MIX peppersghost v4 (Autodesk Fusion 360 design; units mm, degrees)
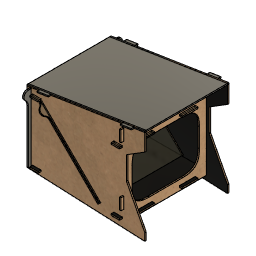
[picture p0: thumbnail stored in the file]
parameter "mat" = 3.175
parameter "device" = 165.1
parameter "chip" = 2.54
sketch "Sketch1" plane through (0, 0, 0) normal (0, 0, 1) x axis (1, 0, 0)
  line L1 (82.55, 82.55) -> (-82.55, 82.55)
  line L2 (82.55, -82.55) -> (82.55, 82.55)
  line L3 (-82.55, -82.55) -> (82.55, -82.55)
  line L4 (-82.55, 82.55) -> (-82.55, -82.55)
  line L5 (82.55, -82.55) -> (-82.55, 82.55)
  line L6 (-82.55, -82.55) -> (82.55, 82.55)
  line L7 (-101.6, -101.6) -> (101.6, -101.6)
  line L8 (-101.6, 101.6) -> (-101.6, -101.6)
  line L9 (101.6, 101.6) -> (-101.6, 101.6)
  line L10 (101.6, -101.6) -> (101.6, 101.6)
  point P6 (0, 0)
  point P1 (0, 0)
  horizontal L1
  perpendicular L1 L2
  parallel L1 L3
  parallel L2 L4
  coincident L5 P6
  coincident L6 P6
  coincident P1 P6
  dimension "d3" distance L2 L4 = 165.1 (= "device")
  dimension "d4" distance L1 L3 = 165.1 (= "device")
  dimension "d5" = -19.05
extrude "Extrude1" new body sketch "Sketch1" profile of L1 L2 L3 L4 L9 L8 L7 L10 along normal blind 3.175 bodies "top glass"
sketch "Sketch5" plane through (0, 0, 3.175) normal (0, 0, 1) x axis (-1, 0, 0)
  line L1 (101.6, -101.6) -> (-101.6, -101.6)
  line L2 (101.6, 101.6) -> (101.6, -101.6)
  line L3 (-101.6, 101.6) -> (101.6, 101.6)
  line L4 (-101.6, -101.6) -> (-101.6, 101.6)
  line L5 (-82.55, 92.075) -> (82.55, 92.075)
  line L6 (-82.55, 101.6) -> (-82.55, 92.075)
  line L7 (82.55, 101.6) -> (-82.55, 101.6)
  line L8 (82.55, 92.075) -> (82.55, 101.6)
  line L9 (-2.5, 0) -> (-20, 0)
  line L10 (82.55, -101.6) -> (-82.55, -101.6)
  line L11 (82.55, -92.075) -> (82.55, -101.6)
  line L12 (-82.55, -101.6) -> (-82.55, -92.075)
  line L13 (-82.55, -92.075) -> (82.55, -92.075)
  point P6 (82.55, 92.075)
  point P14 (82.55, -92.075)
  point P7 (-82.55, 92.075)
  point P15 (-82.55, -92.075)
  point P8 (-82.55, 101.6)
  point P12 (-82.55, -101.6)
  point P9 (82.55, 101.6)
  point P13 (82.55, -101.6)
  horizontal L5
  vertical L6
  horizontal L7
  vertical L8
  midpoint L3 L7
  symmetric P6 L9 P14
  symmetric P7 L9 P15
  symmetric P8 L9 P12
  symmetric P9 L9 P13
  dimension "d14" distance L5 L7 = 9.525 (= "mat + 0.25 in")
  dimension "d15" distance L2 L8 = 19.05
extrude "Extrude3" cut sketch "Sketch5" profile of L1 L3 L5 L6 L7 L8 L10 L11 L12 L13 to an object
work_plane "WorkPlane2" AlongDistance -92.075
sketch "Sketch6" plane through (0, -92.075, 0) normal (0, 1, 0) x axis (1, 0, 0)
  line L1 (152.4, -57.2749) -> (-114.3, -57.2749)
  line L2 (152.4, 158.6251) -> (152.4, -57.2749)
  line L3 (-114.3, 158.6251) -> (152.4, 158.6251)
  line L4 (-114.3, -57.2749) -> (-114.3, 158.6251)
  line L5 (-82.55, 0) -> (82.55, 0)
  line L6 (82.55, -3.175) -> (-82.55, -3.175)
  line L7 (-82.55, -3.175) -> (-101.6, -3.175)
  line L8 (-101.6, -3.175) -> (-101.6, 0)
  line L9 (-101.6, 0) -> (-82.55, 0)
  line L10 (82.55, 0) -> (101.6, 0)
  line L11 (101.6, -3.175) -> (101.6, 0)
  line L12 (101.6, -3.175) -> (82.55, -3.175)
  line L13 (-114.3, -15.4458) -> (152.4, -57.2749)
  line L14 (-114.3, 146.7191) -> (152.4, 158.6251)
  line L15 (110.9761, 61.5737) -> (152.4, 141.4625)
  line L16 (110.9761, 9.6217) -> (110.9761, 61.5737)
  line L17 (152.4, -16.1863) -> (110.9761, 9.6217)
  line L18 (57.3922, 143.0683) -> (-80.2184, 5.4578)
  line L19 (104.4264, 125.521) -> (104.4264, 5.9873)
  point P14 (-114.3, -15.4458)
  point P15 (-114.3, 146.7191)
  point P16 (152.4, 141.4625)
  point P19 (152.4, -16.1863)
  point P11 (-101.6, 0)
  point P12 (101.6, 0)
  horizontal L1
  vertical L2
  horizontal L3
  vertical L4
  coincident L4 P14
  coincident L4 P15
  coincident L2 P16
  parallel L2 L16
  coincident L2 P19
  perpendicular L5 L19
  dimension "d19" distance L4 P11 = 12.7
  dimension "d20" distance L2 P12 = 50.8
  dimension "d21" distance L1 L3 = 215.9
  dimension "d22" angle L5 L18 = 45
extrude "Extrude4" new body sketch "Sketch6" profile of L2 L4 L5 L6 L7 L8 L9 L10 L11 L12 L13 L14 L15 L16 L17 no distance stored bodies "side1"
mirror "Mirror1" mirrorStitchTolerance 0.1016 bodies "side2"
combine "Combine1"
combine "Combine2"
sketch "Sketch8" plane through (0, 0, 3.175) normal (0, 0, 1) x axis (-1, 0, 0)
  line L1 (-82.55, 101.6) -> (-82.55, 92.075)
  line L2 (-101.6, 101.6) -> (-82.55, 101.6)
  line L3 (-101.6, -101.6) -> (-101.6, 101.6)
  line L4 (-82.55, -101.6) -> (-101.6, -101.6)
  line L5 (-82.55, -92.075) -> (-82.55, -101.6)
  line L6 (82.55, -92.075) -> (-82.55, -92.075)
  line L7 (82.55, -101.6) -> (82.55, -92.075)
  line L8 (101.6, -101.6) -> (82.55, -101.6)
  line L9 (101.6, 101.6) -> (101.6, -101.6)
  line L10 (82.55, 101.6) -> (101.6, 101.6)
  line L11 (82.55, 92.075) -> (82.55, 101.6)
  line L12 (-82.55, 92.075) -> (82.55, 92.075)
  line L13 (-101.6, 66.675) -> (-111.125, 66.675)
  line L14 (-101.6, 31.115) -> (-101.6, 66.675)
  line L15 (-111.125, 31.115) -> (-101.6, 31.115)
  line L16 (-111.125, 66.675) -> (-111.125, 31.115)
  line L17 (114.3, 92.075) -> (-152.4, 92.075)
  line L18 (-152.4, 95.25) -> (-152.4, 92.075)
  line L19 (-152.4, 95.25) -> (114.3, 95.25)
  line L20 (114.3, 95.25) -> (114.3, 92.075)
  line L21 (-2.5, 0) -> (-20, 0)
  line L22 (-101.6, -31.115) -> (-101.6, -66.675)
  line L23 (-111.125, -31.115) -> (-101.6, -31.115)
  line L24 (-111.125, -66.675) -> (-111.125, -31.115)
  line L25 (-101.6, -66.675) -> (-111.125, -66.675)
  point P14 (-111.125, 66.675)
  point P27 (-111.125, -66.675)
  point P15 (-101.6, 66.675)
  point P24 (-101.6, -66.675)
  point P16 (-101.6, 31.115)
  point P25 (-101.6, -31.115)
  point P17 (-111.125, 31.115)
  point P26 (-111.125, -31.115)
  horizontal L13
  vertical L14
  horizontal L15
  vertical L16
  collinear L3 L14
  symmetric P14 L21 P27
  symmetric P15 L21 P24
  symmetric P16 L21 P25
  symmetric P17 L21 P26
  dimension "d27" distance L13 L17 = 25.4
  dimension "d28" distance L14 L16 = 9.525 (= "mat + 0.25 in")
extrude "Extrude5" add sketch "Sketch8" profile of L3 L13 L14 L15 L16 L22 L23 L24 L25 to an object
copy_paste_bodies "CopyPasteBodies2"
move "Move2"
combine "Combine5"
combine "Combine6"
sketch "Sketch9" plane through (101.6, 0, 0) normal (1, 0, 0) x axis (0, 1, 0)
  line L1 (31.115, 3.175) -> (31.115, 0)
  line L2 (-31.115, 3.175) -> (31.115, 3.175)
  line L3 (-31.115, 0) -> (-31.115, 3.175)
  line L4 (31.115, 0) -> (-31.115, 0)
  line L5 (-101.6, 3.175) -> (-101.6, 0)
  line L6 (101.6, 0) -> (-101.6, 0)
  line L7 (-101.6, 3.175) -> (101.6, 3.175)
  line L8 (101.6, 3.175) -> (101.6, 0)
  line L9 (-92.075, -146.7191) -> (-92.075, -158.6251)
  line L10 (-92.075, 15.4458) -> (-92.075, -146.7191)
  line L11 (-92.075, 15.4458) -> (-92.075, 57.2749)
  line L12 (-95.25, -158.6251) -> (-92.075, -158.6251)
  line L13 (-95.25, -158.6251) -> (-95.25, -146.7191)
  line L14 (-95.25, -146.7191) -> (-95.25, 15.4458)
  line L15 (-95.25, 15.4458) -> (-95.25, 57.2749)
  line L16 (-95.25, 57.2749) -> (-92.075, 57.2749)
  line L17 (92.075, 15.4458) -> (92.075, 57.2749)
  line L18 (92.075, 15.4458) -> (92.075, -146.7191)
  line L19 (92.075, -146.7191) -> (92.075, -158.6251)
  line L20 (95.25, -158.6251) -> (95.25, -146.7191)
  line L21 (95.25, -158.6251) -> (92.075, -158.6251)
  line L22 (95.25, -146.7191) -> (95.25, 15.4458)
  line L23 (95.25, 57.2749) -> (92.075, 57.2749)
  line L24 (95.25, 15.4458) -> (95.25, 57.2749)
  line L25 (-92.075, -146.7191) -> (92.075, -146.7191)
  line L26 (-92.075, 45.8529) -> (-92.075, -146.7191)
  line L27 (92.075, 45.8529) -> (-92.075, 45.8529)
  line L28 (92.075, -146.7191) -> (92.075, 45.8529)
  line L29 (-101.6, 39.02) -> (-92.075, 39.02)
  line L30 (-101.6, 13.62) -> (-101.6, 39.02)
  line L31 (-92.075, 13.62) -> (-101.6, 13.62)
  line L32 (-92.075, 39.02) -> (-92.075, 13.62)
  line L33 (-101.6, -119.6596) -> (-92.075, -119.6596)
  line L34 (-101.6, -94.2596) -> (-101.6, -119.6596)
  line L35 (-92.075, -94.2596) -> (-101.6, -94.2596)
  line L36 (-92.075, -119.6596) -> (-92.075, -94.2596)
  line L37 (0, -146.7191) -> (0, 45.8529)
  line L38 (92.075, 39.02) -> (92.075, 13.62)
  line L39 (101.6, 39.02) -> (92.075, 39.02)
  line L40 (92.075, 13.62) -> (101.6, 13.62)
  line L41 (101.6, 13.62) -> (101.6, 39.02)
  line L42 (92.075, -119.6596) -> (92.075, -94.2596)
  line L43 (101.6, -119.6596) -> (92.075, -119.6596)
  line L44 (92.075, -94.2596) -> (101.6, -94.2596)
  line L45 (101.6, -94.2596) -> (101.6, -119.6596)
  point P28 (-92.075, 45.8529)
  point P20 (92.075, -146.7191)
  point P26 (92.075, -146.7191)
  point P30 (-92.075, 39.02)
  point P34 (-92.075, -119.6596)
  point P38 (0, 45.8529)
  point P39 (0, -146.7191)
  point P41 (92.075, 39.02)
  point P31 (-101.6, 39.02)
  point P42 (101.6, 39.02)
  point P32 (-101.6, 13.62)
  point P43 (101.6, 13.62)
  point P33 (-92.075, 13.62)
  point P40 (92.075, 13.62)
  point P45 (92.075, -119.6596)
  point P35 (-101.6, -119.6596)
  point P46 (101.6, -119.6596)
  point P36 (-101.6, -94.2596)
  point P47 (101.6, -94.2596)
  point P37 (-92.075, -94.2596)
  point P44 (92.075, -94.2596)
  horizontal L25
  vertical L26
  horizontal L27
  vertical L28
  coincident L11 P28
  coincident P20 P26
  horizontal L29
  vertical L30
  horizontal L31
  vertical L32
  coincident L26 P30
  horizontal L33
  vertical L34
  horizontal L35
  vertical L36
  coincident L10 P34
  midpoint L27 P38
  midpoint L25 P39
  symmetric P30 L37 P41
  symmetric P31 L37 P42
  symmetric P32 L37 P43
  symmetric P33 L37 P40
  symmetric P34 L37 P45
  symmetric P35 L37 P46
  symmetric P36 L37 P47
  symmetric P37 L37 P44
  dimension "d31" distance L29 L31 = 25.4
  dimension "d32" distance L26 L30 = 9.525 (= "mat + 0.25 in")
  dimension "d33" distance L33 L35 = 25.4
  dimension "d34" distance L26 L34 = 9.525 (= "mat + 0.25 in")
extrude "Extrude6" new body sketch "Sketch9" profile of L1 L2 L3 L4 L6 L7 L10 L11 L14 L15 L17 L18 L22 L24 L25 L26 L27 L28 L29 L30 L31 L32 L33 L34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 along normal blind 3.175 (= "mat") bodies "faceplat"
combine "Combine7"
combine "Combine8"
combine "Combine11"
combine "Combine12"
sketch "Sketch11" plane through (104.775, 0, 0) normal (1, 0, 0) x axis (0, 1, 0)
  line L1 (31.115, -136.525) -> (31.115, -139.7)
  line L2 (66.675, -136.525) -> (31.115, -136.525)
  line L3 (66.675, -139.7) -> (66.675, -136.525)
  line L4 (31.115, -139.7) -> (66.675, -139.7)
  line L5 (-66.675, -136.525) -> (-66.675, -139.7)
  line L6 (-31.115, -136.525) -> (-66.675, -136.525)
  line L7 (-31.115, -139.7) -> (-31.115, -136.525)
  line L8 (-66.675, -139.7) -> (-31.115, -139.7)
  line L9 (31.115, 3.175) -> (31.115, 0)
  line L10 (66.675, 3.175) -> (31.115, 3.175)
  line L11 (66.675, 0) -> (66.675, 3.175)
  line L12 (31.115, 0) -> (66.675, 0)
  line L13 (-66.675, 3.175) -> (-66.675, 0)
  line L14 (-31.115, 3.175) -> (-66.675, 3.175)
  line L15 (-31.115, 0) -> (-31.115, 3.175)
  line L16 (-66.675, 0) -> (-31.115, 0)
  line L17 (101.6, -119.6596) -> (92.075, -119.6596)
  line L18 (101.6, -94.2596) -> (101.6, -119.6596)
  line L19 (92.075, -94.2596) -> (101.6, -94.2596)
  line L20 (92.075, 13.62) -> (92.075, -94.2596)
  line L21 (101.6, 13.62) -> (92.075, 13.62)
  line L22 (101.6, 39.02) -> (101.6, 13.62)
  line L23 (92.075, 39.02) -> (101.6, 39.02)
  line L24 (92.075, 45.8529) -> (92.075, 39.02)
  line L25 (-92.075, 45.8529) -> (92.075, 45.8529)
  line L26 (-92.075, 39.02) -> (-92.075, 45.8529)
  line L27 (-101.6, 39.02) -> (-92.075, 39.02)
  line L28 (-101.6, 13.62) -> (-101.6, 39.02)
  line L29 (-92.075, 13.62) -> (-101.6, 13.62)
  line L30 (-92.075, -94.2596) -> (-92.075, 13.62)
  line L31 (-101.6, -94.2596) -> (-92.075, -94.2596)
  line L32 (-101.6, -119.6596) -> (-101.6, -94.2596)
  line L33 (-92.075, -119.6596) -> (-101.6, -119.6596)
  line L34 (-92.075, -146.7191) -> (-92.075, -119.6596)
  line L35 (92.075, -146.7191) -> (-92.075, -146.7191)
  line L36 (92.075, -119.6596) -> (92.075, -146.7191)
  line L37 (76.2, -5.08) -> (-76.2, -5.08)
  line L38 (76.2, -124.46) -> (76.2, -5.08)
  line L39 (-76.2, -124.46) -> (76.2, -124.46)
  line L40 (-76.2, -5.08) -> (-76.2, -124.46)
  horizontal L37
  vertical L38
  horizontal L39
  vertical L40
extrude "Extrude7" cut sketch "Sketch11" profile of L37 L38 L39 L40 to an object
fillet "Fillet1" radius 38.1
sketch "Sketch12" plane through (0, 0, 0) normal (0, 1, 0) x axis (1, 0, 0)
  line L1 (52.4196, 133.0004) -> (-80.5808, 0)
  line L2 (50.1745, 135.2455) -> (52.4196, 133.0004)
  line L3 (-82.8258, 2.2451) -> (50.1745, 135.2455)
  line L4 (-80.5808, 0) -> (-82.8258, 2.2451)
  line L5 (82.55, 0) -> (-82.55, 0)
  point P2 (-80.5808, 0)
  point P5 (-82.8258, 2.2451)
  perpendicular L1 L2
  parallel L1 L3
  parallel L2 L4
  coincident P2 L5
  dimension "d41" distance P2 P5 = 3.175
  dimension "d42" angle L1 L5 = 45
extrude "Extrude8" new body sketch "Sketch12" profile of L1 L2 L3 L4 distance 99.06 bodies "reflector"
sketch "Sketch13" plane through (-40.2904, 0, -40.2904) normal (0.7071, 0, 0.7071) x axis (0, 1, 0)
  line L1 (99.06, -131.1117) -> (-99.06, -131.1117)
  line L2 (99.06, 56.9792) -> (99.06, -131.1117)
  line L3 (-99.06, 56.9792) -> (99.06, 56.9792)
  line L4 (-99.06, -131.1117) -> (-99.06, 56.9792)
  line L5 (-92.075, -22.9237) -> (-92.075, -219.928)
  line L6 (-92.075, 91.7442) -> (-92.075, -22.9237)
  line L7 (-95.25, -219.928) -> (-92.075, -219.928)
  line L8 (-95.25, -219.928) -> (-95.25, -22.9237)
  line L9 (-95.25, -22.9237) -> (-95.25, 91.7442)
  line L10 (-95.25, 91.7442) -> (-92.075, 91.7442)
  line L11 (-92.075, -131.1117) -> (-95.25, -131.1117)
  line L12 (-92.075, -121.5867) -> (-92.075, -131.1117)
  line L13 (-95.25, -121.5867) -> (-92.075, -121.5867)
  line L14 (-95.25, -131.1117) -> (-95.25, -121.5867)
  line L15 (0, -106.68) -> (0, -131.1117)
  line L16 (0, -106.68) -> (0, -131.1117)
  line L17 (92.075, -121.5867) -> (92.075, -131.1117)
  line L18 (95.25, -121.5867) -> (92.075, -121.5867)
  line L19 (92.075, -131.1117) -> (95.25, -131.1117)
  line L20 (95.25, -131.1117) -> (95.25, -121.5867)
  circle C1 centre (99.06, 41.3822) radius 9.525
  circle C2 centre (-99.06, 41.3822) radius 9.525
  point P12 (-95.25, -131.1117)
  point P16 (0, -131.1117)
  point P23 (95.25, -131.1117)
  point P13 (-92.075, -131.1117)
  point P20 (92.075, -131.1117)
  point P14 (-92.075, -121.5867)
  point P21 (92.075, -121.5867)
  point P15 (-95.25, -121.5867)
  point P22 (95.25, -121.5867)
  point P18 (0, -131.1117)
  point P17 (0, -106.68)
  point P19 (0, -106.68)
  point P24 (99.06, 41.3822)
  horizontal L11
  vertical L12
  horizontal L13
  vertical L14
  coincident L8 P12
  coincident L1 P12
  midpoint L1 P16
  perpendicular L1 L15
  symmetric P12 L15 P23
  symmetric P13 L15 P20
  symmetric P14 L15 P21
  symmetric P15 L15 P22
  symmetric P16 L15 P18
  symmetric P17 L15 P19
  coincident L2 P24
  symmetric L16 C1 C2
  dimension "d45" distance P12 P15 = 9.525
  dimension "d46" distance L12 L14 = 3.175 (= "mat")
  dimension "d49" diameter C1 = 19.05
combine "Combine13"
combine "Combine14"
extrude "Extrude9" cut sketch "Sketch13" profile of L1 L5 L8 L11 L12 L13 L14 L17 L18 L19 L20 to an object
extrude "Extrude10" add sketch "Sketch13" profile of L2 L4 C1 C2 to an object
fillet "Fillet2" radius 7.62
work_plane "WorkPlane3" AlongDistance 50.8
sketch "Sketch14" plane through (19.05, -146.05, -50.6751) normal (0, -1, 0) x axis (-1, 0, 0)
sketch "side panel" plane through (19.05, -146.05, -50.6751) normal (0, -1, 0) x axis (-1, 0, 0)
  line L1 (99.6308, -50.6751) -> (-33.3696, 82.3253)
  line L2 (101.8758, -48.4301) -> (99.6308, -50.6751)
  line L3 (-31.1245, 84.5703) -> (101.8758, -48.4301)
  line L4 (-33.3696, 82.3253) -> (-31.1245, 84.5703)
  line L5 (-85.725, 68.9845) -> (-82.55, 68.9845)
  line L6 (-85.725, -64.2951) -> (-82.55, -64.2951)
  line L7 (-82.55, -64.2951) -> (-82.55, -89.6951)
  line L8 (-82.55, 68.9845) -> (-82.55, 43.5845)
  line L9 (-85.725, -89.6951) -> (-85.725, -64.2951)
  line L10 (-82.55, 43.5845) -> (-85.725, 43.5845)
  line L11 (-82.55, -89.6951) -> (-85.725, -89.6951)
  line L12 (-85.725, 43.5845) -> (-85.725, 68.9845)
  line L13 (-63.5, 85.8499) -> (-82.55, 85.8499)
  line L14 (-63.5, 89.0249) -> (-63.5, 85.8499)
  line L15 (-82.55, 89.0249) -> (-63.5, 89.0249)
  line L16 (-82.55, 85.8499) -> (-82.55, 89.0249)
  line L17 (-82.55, -53.8501) -> (-82.55, -50.6751)
  line L18 (-63.5, -53.8501) -> (-82.55, -53.8501)
  line L19 (-63.5, -50.6751) -> (-63.5, -53.8501)
  line L20 (-82.55, -50.6751) -> (-63.5, -50.6751)
  line L21 (-133.35, 107.95) -> (-133.35, 90.7873)
  line L22 (133.35, 96.0439) -> (-133.35, 107.95)
  line L23 (133.35, -66.121) -> (133.35, 96.0439)
  line L24 (133.35, -66.121) -> (-133.35, -107.95)
  line L25 (-133.35, -66.8614) -> (-133.35, -107.95)
  line L26 (-133.35, -66.8614) -> (-91.9261, -41.0534)
  line L27 (-91.9261, -41.0534) -> (-91.9261, 10.8985)
  line L28 (-91.9261, 10.8985) -> (-133.35, 90.7873)
  line L29 (120.65, -53.8501) -> (101.6, -53.8501)
  line L30 (120.65, -50.6751) -> (120.65, -53.8501)
  line L31 (101.6, -50.6751) -> (120.65, -50.6751)
  line L32 (101.6, -53.8501) -> (101.6, -50.6751)
  line L33 (120.65, 85.8499) -> (101.6, 85.8499)
  line L34 (120.65, 89.0249) -> (120.65, 85.8499)
  line L35 (101.6, 89.0249) -> (120.65, 89.0249)
  line L36 (101.6, 85.8499) -> (101.6, 89.0249)
work_plane "WorkPlane4" AlongDistance 50.8
sketch "top glass" plane through (4.7625, 0, 53.975) normal (0, 0, 1) x axis (1, 0, 0)
  line L1 (106.3625, 66.675) -> (106.3625, 31.115)
  line L2 (96.8375, 66.675) -> (106.3625, 66.675)
  line L3 (106.3625, 31.115) -> (96.8375, 31.115)
  line L4 (96.8375, 66.675) -> (96.8375, 101.6)
  line L5 (96.8375, -31.115) -> (96.8375, 31.115)
  line L6 (106.3625, -31.115) -> (106.3625, -66.675)
  line L7 (96.8375, -31.115) -> (106.3625, -31.115)
  line L8 (106.3625, -66.675) -> (96.8375, -66.675)
  line L9 (96.8375, -101.6) -> (96.8375, -66.675)
  line L10 (-87.3125, -101.6) -> (-87.3125, -92.075)
  line L11 (77.7875, -92.075) -> (77.7875, -101.6)
  line L12 (-87.3125, -92.075) -> (77.7875, -92.075)
  line L13 (-87.3125, 92.075) -> (-87.3125, 101.6)
  line L14 (77.7875, 92.075) -> (-87.3125, 92.075)
  line L15 (77.7875, 101.6) -> (77.7875, 92.075)
  line L16 (-106.3625, -101.6) -> (-87.3125, -101.6)
  line L17 (-106.3625, 101.6) -> (-106.3625, -101.6)
  line L18 (-87.3125, 101.6) -> (-106.3625, 101.6)
  line L19 (96.8375, 101.6) -> (77.7875, 101.6)
  line L20 (77.7875, -101.6) -> (96.8375, -101.6)
work_plane "WorkPlane5" AlongDistance 50.8
sketch "faceplate" plane through (155.575, 0, -50.4331) normal (1, 0, 0) x axis (0, 1, 0)
  curve K1 (38.1, -74.0269) -> (76.2, -35.9269)
  line L1 (76.2, 7.2531) -> (76.2, -35.9269)
  curve K2 (-76.2, -35.9269) -> (-38.1, -74.0269)
  line L2 (38.1, -74.0269) -> (-38.1, -74.0269)
  curve K3 (76.2, 7.2531) -> (38.1, 45.3531)
  line L3 (-38.1, 45.3531) -> (38.1, 45.3531)
  curve K4 (-38.1, 45.3531) -> (-76.2, 7.2531)
  line L4 (-76.2, -35.9269) -> (-76.2, 7.2531)
  line L5 (66.675, -86.0919) -> (66.675, -89.2669)
  line L6 (-31.115, -86.0919) -> (-31.115, -89.2669)
  line L7 (-31.115, -89.2669) -> (-66.675, -89.2669)
  line L8 (66.675, -89.2669) -> (31.115, -89.2669)
  line L9 (-66.675, -86.0919) -> (-31.115, -86.0919)
  line L10 (31.115, -89.2669) -> (31.115, -86.0919)
  line L11 (-66.675, -89.2669) -> (-66.675, -86.0919)
  line L12 (31.115, -86.0919) -> (66.675, -86.0919)
  line L13 (92.075, -96.286) -> (92.075, -69.2265)
  line L14 (-92.075, -96.286) -> (92.075, -96.286)
  line L15 (-92.075, -69.2265) -> (-92.075, -96.286)
  line L16 (-101.6, -69.2265) -> (-92.075, -69.2265)
  line L17 (-101.6, -43.8265) -> (-101.6, -69.2265)
  line L18 (-92.075, -43.8265) -> (-101.6, -43.8265)
  line L19 (-92.075, 64.0531) -> (-92.075, -43.8265)
  line L20 (-92.075, 64.0531) -> (-101.6, 64.0531)
  line L21 (-101.6, 64.0531) -> (-101.6, 89.4531)
  line L22 (-101.6, 89.4531) -> (-92.075, 89.4531)
  line L23 (-92.075, 96.286) -> (-92.075, 89.4531)
  line L24 (92.075, 96.286) -> (-92.075, 96.286)
  line L25 (92.075, 89.4531) -> (92.075, 96.286)
  line L26 (101.6, 89.4531) -> (92.075, 89.4531)
  line L27 (101.6, 64.0531) -> (101.6, 89.4531)
  line L28 (92.075, 64.0531) -> (101.6, 64.0531)
  line L29 (92.075, -43.8265) -> (92.075, 64.0531)
  line L30 (92.075, -43.8265) -> (101.6, -43.8265)
  line L31 (101.6, -43.8265) -> (101.6, -69.2265)
  line L32 (101.6, -69.2265) -> (92.075, -69.2265)
  line L33 (66.675, 53.6081) -> (66.675, 50.4331)
  line L34 (31.115, 53.6081) -> (66.675, 53.6081)
  line L35 (31.115, 50.4331) -> (31.115, 53.6081)
  line L36 (66.675, 50.4331) -> (31.115, 50.4331)
  line L37 (-31.115, 53.6081) -> (-31.115, 50.4331)
  line L38 (-66.675, 53.6081) -> (-31.115, 53.6081)
  line L39 (-66.675, 50.4331) -> (-66.675, 53.6081)
  line L40 (-31.115, 50.4331) -> (-66.675, 50.4331)
work_plane "WorkPlane6" AlongDistance 50.8
sketch "reflector" plane through (21.8404, 0, -30.5792) normal (0.7071, 0, 0.7071) x axis (0.7071, 0, -0.7071)
  line L1 (-94.0455, 99.06) -> (-93.807, 99.06)
  line L2 (-63.0898, 99.06) -> (94.0455, 99.06)
  line L3 (-93.807, -99.06) -> (-94.0455, -99.06)
  line L4 (94.0455, -99.06) -> (-63.0898, -99.06)
  line L5 (84.5205, -95.25) -> (84.5205, -92.075)
  line L6 (94.0455, -95.25) -> (84.5205, -95.25)
  line L7 (84.5205, -92.075) -> (94.0455, -92.075)
  line L8 (84.5205, 95.25) -> (94.0455, 95.25)
  line L9 (84.5205, 92.075) -> (84.5205, 95.25)
  line L10 (94.0455, 92.075) -> (84.5205, 92.075)
  line L11 (94.0455, -95.25) -> (94.0455, -99.06)
  line L12 (-94.0455, -99.06) -> (-94.0455, 99.06)
  line L13 (94.0455, 99.06) -> (94.0455, 95.25)
  line L14 (94.0455, 92.075) -> (94.0455, -92.075)
  arc A1 centre (-93.807, -106.68) radius 7.62 clockwise from (-93.807, -99.06) to (-86.981, -103.2933)
  arc A2 centre (-78.4484, -99.06) radius 9.525 clockwise from (-69.9159, -103.2933) to (-86.981, -103.2933)
  arc A3 centre (-63.0898, -106.68) radius 7.62 clockwise from (-69.9159, -103.2933) to (-63.0898, -99.06)
  arc A4 centre (-93.807, 106.68) radius 7.62 clockwise from (-86.981, 103.2933) to (-93.807, 99.06)
  arc A5 centre (-78.4484, 99.06) radius 9.525 clockwise from (-86.981, 103.2933) to (-69.9159, 103.2933)
  arc A6 centre (-63.0898, 106.68) radius 7.62 clockwise from (-63.0898, 99.06) to (-69.9159, 103.2933)
sketch "Sketch19" plane through (-5.1085, 0, 32.5714) normal (-0.1549, 0, 0.9879) x axis (0, -1, 0)
  line L1 (92.075, -110.5264) -> (92.075, 159.4339)
  line L2 (95.25, -110.5264) -> (92.075, -110.5264)
  line L3 (95.25, 159.4339) -> (95.25, -110.5264)
  line L4 (92.075, 159.4339) -> (95.25, 159.4339)
  line L5 (-92.075, 159.4339) -> (-92.075, -110.5264)
  line L6 (-95.25, 159.4339) -> (-92.075, 159.4339)
  line L7 (-95.25, -110.5264) -> (-95.25, 159.4339)
  line L8 (-92.075, -110.5264) -> (-95.25, -110.5264)
  line L9 (-95.25, -110.5264) -> (95.25, -110.5264)
  line L10 (-95.25, 159.4339) -> (-95.25, -110.5264)
  line L11 (95.25, 159.4339) -> (-95.25, 159.4339)
  line L12 (95.25, -110.5264) -> (95.25, 159.4339)
  line L13 (101.6, 109.5556) -> (92.075, 109.5556)
  line L14 (92.075, -81.0611) -> (101.6, -81.0611)
  line L15 (-92.075, 109.5556) -> (-101.6, 109.5556)
  line L16 (-101.6, -81.0611) -> (-92.075, -81.0611)
  line L17 (92.075, 109.5556) -> (101.6, 109.5556)
  line L18 (92.075, 134.9545) -> (92.075, 109.5556)
  line L19 (101.6, 134.9545) -> (92.075, 134.9545)
  line L20 (101.6, 109.5556) -> (101.6, 134.9545)
  line L21 (92.075, -81.0611) -> (101.6, -81.0611)
  line L22 (92.075, -55.6611) -> (92.075, -81.0611)
  line L23 (101.6, -55.6611) -> (92.075, -55.6611)
  line L24 (101.6, -81.0611) -> (101.6, -55.6611)
  line L25 (0, 159.4339) -> (0, -110.5264)
  line L26 (-92.075, -55.6611) -> (-92.075, -81.0611)
  line L27 (-101.6, -55.6611) -> (-92.075, -55.6611)
  line L28 (-92.075, -81.0611) -> (-101.6, -81.0611)
  line L29 (-101.6, -81.0611) -> (-101.6, -55.6611)
  line L30 (-92.075, 134.9545) -> (-92.075, 109.5556)
  line L31 (-101.6, 134.9545) -> (-92.075, 134.9545)
  line L32 (-92.075, 109.5556) -> (-101.6, 109.5556)
  line L33 (-101.6, 109.5556) -> (-101.6, 134.9545)
  point P8 (-95.25, 159.4339)
  point P12 (-95.25, 159.4339)
  point P4 (95.25, -110.5264)
  point P10 (95.25, -110.5264)
  point P24 (92.075, 134.9545)
  point P15 (101.6, 109.5556)
  point P22 (101.6, 109.5556)
  point P16 (101.6, -81.0611)
  point P26 (101.6, -81.0611)
  point P30 (0, -110.5264)
  point P31 (0, 159.4339)
  point P39 (-101.6, 109.5556)
  point P23 (92.075, 109.5556)
  point P36 (-92.075, 109.5556)
  point P37 (-92.075, 134.9545)
  point P25 (101.6, 134.9545)
  point P38 (-101.6, 134.9545)
  point P35 (-101.6, -81.0611)
  point P27 (92.075, -81.0611)
  point P32 (-92.075, -81.0611)
  point P28 (92.075, -55.6611)
  point P33 (-92.075, -55.6611)
  point P29 (101.6, -55.6611)
  point P34 (-101.6, -55.6611)
  horizontal L9
  vertical L10
  horizontal L11
  vertical L12
  coincident P8 P12
  coincident P4 P10
  horizontal L17
  vertical L18
  horizontal L19
  vertical L20
  coincident L1 P24
  coincident P15 P22
  horizontal L21
  vertical L22
  horizontal L23
  vertical L24
  coincident P16 P26
  midpoint L9 P30
  midpoint L11 P31
  symmetric P22 L25 P39
  symmetric P23 L25 P36
  symmetric P24 L25 P37
  symmetric P25 L25 P38
  symmetric P26 L25 P35
  symmetric P27 L25 P32
  symmetric P28 L25 P33
  symmetric P29 L25 P34
  dimension "d58" distance P26 P29 = 25.4
extrude "Extrude11" new body sketch "Sketch19" profile of L1 L2 L3 L4 L5 L6 L7 L8 L9 L10 L11 L12 L13 L14 L15 L16 L17 L18 L19 L20 L21 L22 L23 L24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 no distance stored bodies "chip top"
work_plane "WorkPlane7" AlongDistance 50.8
sketch "chiptop" plane through (11.1788, 0, 86.5468) normal (-0.1549, 0, 0.9879) x axis (0, -1, 0)
  line L1 (-101.6, 110.5007) -> (-95.25, 110.5007)
  line L2 (-101.6, 85.1018) -> (-101.6, 110.5007)
  line L3 (-95.25, 85.1018) -> (-101.6, 85.1018)
  line L4 (-95.25, -80.1149) -> (-95.25, 85.1018)
  line L5 (-101.6, -80.1149) -> (-95.25, -80.1149)
  line L6 (-101.6, -105.5149) -> (-101.6, -80.1149)
  line L7 (-95.25, -105.5149) -> (-101.6, -105.5149)
  line L8 (-95.25, -134.9801) -> (-95.25, -105.5149)
  line L9 (95.25, -134.9801) -> (-95.25, -134.9801)
  line L10 (95.25, -105.5149) -> (95.25, -134.9801)
  line L11 (101.6, -105.5149) -> (95.25, -105.5149)
  line L12 (101.6, -80.1149) -> (101.6, -105.5149)
  line L13 (95.25, -80.1149) -> (101.6, -80.1149)
  line L14 (95.25, 85.1018) -> (95.25, -80.1149)
  line L15 (101.6, 85.1018) -> (95.25, 85.1018)
  line L16 (101.6, 110.5007) -> (101.6, 85.1018)
  line L17 (95.25, 110.5007) -> (101.6, 110.5007)
  line L18 (95.25, 134.9801) -> (95.25, 110.5007)
  line L19 (-95.25, 134.9801) -> (95.25, 134.9801)
  line L20 (-95.25, 110.5007) -> (-95.25, 134.9801)
sketch "Sketch21" plane through (0, 0, 0) normal (0, 1, 0) x axis (1, 0, 0)
  line L1 (52.4196, 133.0004) -> (-80.5808, 0)
  line L2 (50.1745, 135.2455) -> (52.4196, 133.0004)
  line L3 (-82.8258, 2.2451) -> (50.1745, 135.2455)
  line L4 (-80.5808, 0) -> (-82.8258, 2.2451)
  line L5 (104.775, -39.02) -> (101.6, -39.02)
  line L6 (104.775, 94.2596) -> (101.6, 94.2596)
  line L7 (104.775, 119.6596) -> (104.775, 94.2596)
  line L8 (101.6, 94.2596) -> (101.6, 119.6596)
  line L9 (101.6, -39.02) -> (101.6, -13.62)
  line L10 (101.6, -13.62) -> (104.775, -13.62)
  line L11 (101.6, 119.6596) -> (104.775, 119.6596)
  line L12 (104.775, -13.62) -> (104.775, -39.02)
  line L13 (101.6, 0) -> (101.6, -3.175)
  line L14 (82.55, 0) -> (101.6, 0)
  line L15 (82.55, -3.175) -> (82.55, 0)
  line L16 (101.6, -3.175) -> (82.55, -3.175)
  line L17 (82.55, 139.7) -> (101.6, 139.7)
  line L18 (82.55, 136.525) -> (82.55, 139.7)
  line L19 (101.6, 136.525) -> (82.55, 136.525)
  line L20 (101.6, 139.7) -> (101.6, 136.525)
  line L21 (152.4, 158.6251) -> (152.4, 141.4625)
  line L22 (110.9761, 61.5737) -> (152.4, 141.4625)
  line L23 (110.9761, 9.6217) -> (110.9761, 61.5737)
  line L24 (152.4, -16.1863) -> (110.9761, 9.6217)
  line L25 (152.4, -16.1863) -> (152.4, -57.2749)
  line L26 (-114.3, -15.4458) -> (152.4, -57.2749)
  line L27 (-114.3, -15.4458) -> (-114.3, 146.7191)
  line L28 (-114.3, 146.7191) -> (152.4, 158.6251)
  line L29 (-101.6, 0) -> (-82.55, 0)
  line L30 (-101.6, -3.175) -> (-101.6, 0)
  line L31 (-82.55, -3.175) -> (-101.6, -3.175)
  line L32 (-82.55, 0) -> (-82.55, -3.175)
  line L33 (-101.6, 139.7) -> (-82.55, 139.7)
  line L34 (-101.6, 136.525) -> (-101.6, 139.7)
  line L35 (-82.55, 136.525) -> (-101.6, 136.525)
  line L36 (-82.55, 139.7) -> (-82.55, 136.525)
  line L37 (-107.95, -12.284) -> (-104.775, -12.284)
  line L38 (-107.95, 140.116) -> (-107.95, -12.284)
  line L39 (-104.775, 140.116) -> (-107.95, 140.116)
  line L40 (-104.775, -12.284) -> (-104.775, 140.116)
  horizontal L37
  vertical L38
  horizontal L39
  vertical L40
  dimension "d63" distance L38 L40 = 3.175 (= "mat")
  dimension "d64" distance L27 L38 = 6.35
  dimension "d65" distance L37 L39 = 152.4
extrude "Extrude12" new body sketch "Sketch21" profile of L37 L38 L39 L40 distance 101.6
sketch "Sketch22" plane through (-107.95, 0, 0) normal (-1, 0, 0) x axis (0, -1, 0)
  line L1 (-101.6, 12.284) -> (101.6, 12.284)
  line L2 (-101.6, -140.116) -> (-101.6, 12.284)
  line L3 (101.6, -140.116) -> (-101.6, -140.116)
  line L4 (101.6, 12.284) -> (101.6, -140.116)
  line L5 (0, 20) -> (0, 2.5)
  circle C1 centre (-101.6, 2.3313) radius 9.9513
  circle C2 centre (101.6, 2.3313) radius 9.9513
  point P6 (-101.6, 2.3313)
  coincident L2 P6
  symmetric C1 L5 C2
extrude "Extrude13" add sketch "Sketch22" profile of L2 L4 C1 C2 to an object
fillet "Fillet3" radius 17.78
combine "Combine15"
combine "Combine16"
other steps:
base_feature "Base Feature" bodies "top glass", "bottom panel"
named bodies: "top glass", "side1", "side2", "bottom panel", "faceplat", "reflector", "chip top"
